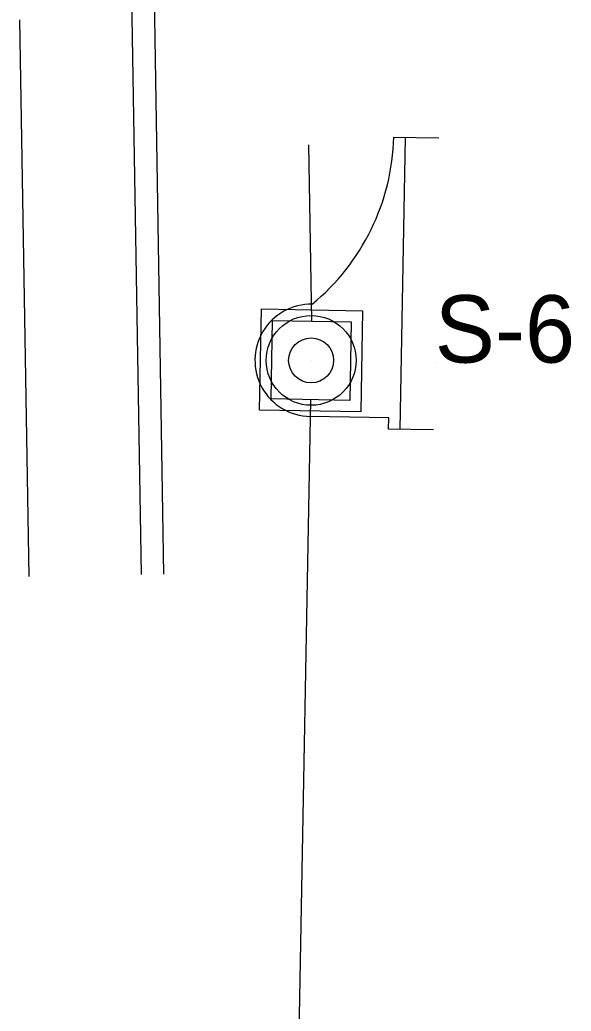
# Model space of a CAD drawing. Extents: x 925371 to 925937, y 853654 to 858024.
# Drawn here: x 925743.7 to 925768.22, y 853893.65 to 853937.78 of the extents above; entities that cross this region are included whole.
import ezdxf

# ---------------------------------------------------------------- set-up
doc = ezdxf.new("R2010")
doc.units = 0
for name, color, linetype in [('GPKDrBack_dp', 7, 'Continuous'), ('GPKDrBottom_dp', 7, 'Continuous'), ('GPKDrCellIns_dp', 7, 'Continuous'), ('GPKDrCentroid_dp', 7, 'Continuous'), ('GPKDrFront_dp', 7, 'Continuous'), ('GPKDrPipe_dp', 7, 'Continuous'), ('GPKDrPipeCir_dp', 7, 'Continuous'), ('InletBottomP', 7, 'Continuous'), ('InletCurb', 7, 'Continuous'), ('NonPlottingEle_dp', 7, 'Continuous'), ('PipeCulvert', 7, 'Continuous'), ('Scratch1_dp', 7, 'Continuous')]:
    doc.layers.add(name, color=color, linetype=linetype)

msp = doc.modelspace()

# ---------------------------------------------------------------- linework, layer by layer
at = {"layer": 'GPKDrBack_dp'}
for p, q in [((925754.159, 853922.667), (925754.159, 853922.667)), ((925754.909, 853922.654), (925754.909, 853922.654))]:
    msp.add_line(p, q, dxfattribs=at)
at = {"layer": 'GPKDrBottom_dp'}
for p, q in [((925756.694, 853924.622), (925756.694, 853924.622)), ((925754.94, 853924.403), (925754.94, 853924.403)), ((925755.27, 853924.062), (925755.27, 853924.062)), ((925756.69, 853924.372), (925756.69, 853924.372)), ((925758.098, 853924.011), (925758.098, 853924.011)), ((925758.439, 853924.341), (925758.439, 853924.341)), ((925754.659, 853922.658), (925754.659, 853922.658)), ((925754.909, 853922.654), (925754.909, 853922.654)), ((925756.658, 853922.623), (925756.658, 853922.623)), ((925756.658, 853922.623), (925756.658, 853922.623)), ((925758.408, 853922.591), (925758.408, 853922.591)), ((925758.658, 853922.587), (925758.658, 853922.587)), ((925755.219, 853921.234), (925755.219, 853921.234)), ((925758.047, 853921.183), (925758.047, 853921.183)), ((925754.877, 853920.904), (925754.877, 853920.904)), ((925756.623, 853920.623), (925756.623, 853920.623)), ((925756.627, 853920.873), (925756.627, 853920.873)), ((925758.377, 853920.841), (925758.377, 853920.841))]:
    msp.add_line(p, q, dxfattribs=at)
at = {"layer": 'GPKDrCellIns_dp'}
for p, q in [((925756.658, 853922.623), (925756.658, 853922.623)), ((925762.157, 853922.524), (925762.157, 853922.524))]:
    msp.add_line(p, q, dxfattribs=at)
at = {"layer": 'GPKDrCentroid_dp'}
msp.add_line((925756.658, 853922.623), (925756.658, 853922.623), dxfattribs=at)
at = {"layer": 'GPKDrFront_dp'}
for p, q in [((925758.408, 853922.591), (925758.408, 853922.591)), ((925762.157, 853922.524), (925762.157, 853922.524))]:
    msp.add_line(p, q, dxfattribs=at)
at = {"layer": 'GPKDrPipe_dp'}
for p, q in [((925755.886, 853924.467), (925755.886, 853924.467)), ((925756.694, 853924.622), (925756.694, 853924.622)), ((925757.443, 853924.462), (925757.443, 853924.462)), ((925755.249, 853924.042), (925755.249, 853924.042)), ((925756.69, 853924.372), (925756.69, 853924.372)), ((925758.077, 853924.032), (925758.077, 853924.032)), ((925754.819, 853923.408), (925754.819, 853923.408)), ((925758.503, 853923.395), (925758.503, 853923.395)), ((925754.659, 853922.658), (925754.659, 853922.658)), ((925754.909, 853922.654), (925754.909, 853922.654)), ((925758.408, 853922.591), (925758.408, 853922.591)), ((925758.658, 853922.587), (925758.658, 853922.587)), ((925754.814, 853921.85), (925754.814, 853921.85)), ((925758.498, 853921.838), (925758.498, 853921.838)), ((925755.239, 853921.213), (925755.239, 853921.213)), ((925758.068, 853921.204), (925758.068, 853921.204)), ((925755.873, 853920.783), (925755.873, 853920.783)), ((925756.623, 853920.623), (925756.623, 853920.623)), ((925756.627, 853920.873), (925756.627, 853920.873)), ((925757.431, 853920.778), (925757.431, 853920.778))]:
    msp.add_line(p, q, dxfattribs=at)
at = {"layer": 'GPKDrPipeCir_dp'}
msp.add_circle((925756.658, 853922.623), 2, dxfattribs=at)
at = {"layer": 'InletBottomP'}
for points in [[(925754.368, 853920.413), (925754.449, 853924.912), (925758.948, 853924.832), (925758.868, 853920.332)], [(925758.377, 853920.841), (925754.877, 853920.904), (925754.94, 853924.403), (925758.439, 853924.341)]]:
    msp.add_lwpolyline(points, close=True, dxfattribs=at)
at = {"layer": 'InletCurb'}
for p, q in [((925760.337, 853932.558), (925762.337, 853932.523)), ((925760.837, 853932.549), (925760.604, 853919.551)), ((925760.113, 853920.06), (925756.614, 853920.123)), ((925760.104, 853919.56), (925760.113, 853920.06)), ((925762.104, 853919.525), (925760.104, 853919.56))]:
    msp.add_line(p, q, dxfattribs=at)
msp.add_circle((925756.658, 853922.623), 1, dxfattribs=at)
for centre, radius, start, end in [((925750.341, 853932.837), 10, 309.512, 358.4024), ((925756.658, 853922.623), 2.5, 88.9741, 268.9741)]:
    msp.add_arc(centre, radius, start, end, dxfattribs=at)
at = {"layer": 'NonPlottingEle_dp'}
for p, q in [((925749.11, 853913.088), (925747.973, 853981.796)), ((925750.109, 853913.105), (925748.973, 853981.813)), ((925744.11, 853913.005), (925743.7, 853937.783))]:
    msp.add_line(p, q, dxfattribs=at)
at = {"layer": 'PipeCulvert'}
msp.add_line((925756.627, 853920.873), (925755.233, 853845.528), dxfattribs=at)
at = {"layer": 'Scratch1_dp'}
msp.add_line((925756.69, 853924.372), (925756.556, 853932.221), dxfattribs=at)

# ---------------------------------------------------------------- texts
at = {"layer": 'NonPlottingEle_dp'}
msp.add_text('S-6', height=3, dxfattribs=at).set_placement((925762.157, 853922.524))

doc.saveas('drawing.dxf')
